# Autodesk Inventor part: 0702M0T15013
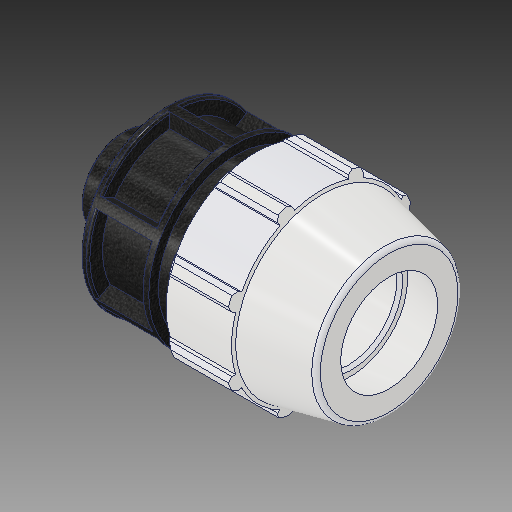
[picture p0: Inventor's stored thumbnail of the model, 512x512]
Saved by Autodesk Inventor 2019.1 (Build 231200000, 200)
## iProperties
Created: 2017-02
Part Number: 0702M0T15013
Material: PVC-Piping
Description: PLASSON MALE ADAPTOR 1 1/2'' - 1 1/4''M
Document SubType Name: Modeling
Designer: KIM
Mass: 92.6774 g
Surface Area: 199.44 cm^2
Volume: 66.1981 cm^3
Density: 1.4 g/cm^3
Appearance: PTFE
Author: KIM
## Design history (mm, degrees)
derived "0702M0T.ipt"
feature "Solid1::0702M0T.ipt"
tag "TaggingFeature1"
body "Solid1"
other parameters: "d2" = 48.1, "d4" = 18.86857, "d5" = 33.02, "d7" = 96.012, "d8" = 72.009, "d9" = 18.86857, "d11" = 3.77371, "d12" = 76.8096, "d13" = 120 deg, "d14" = 72.15, "d15" = 12 deg, "d16" = 86.4108, "d18" = 2.405, "d19" = 35 deg, "d20" = 17.5 deg, "d21" = 89.29116, "d23" = 0, "d25" = 360 deg, "d27" = 1.92024, "d34" = 4.8006, "d36" = 0, "d42" = 33.02, "d43" = 2.88036, "d46" = 1.443, "d51" = 132.08, "d52" = 22.098, "d53" = 0.962, "d55" = 360 deg, "d57" = 41.91, "d58" = 29.337, "d59" = 26.416, "d61" = 27.178, "d_" = 48.1, "E_" = 96.012, "H_" = 132.08, "l_" = 113.03, "l_2" = 22.098, "G_" = 41.91
